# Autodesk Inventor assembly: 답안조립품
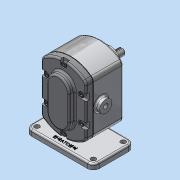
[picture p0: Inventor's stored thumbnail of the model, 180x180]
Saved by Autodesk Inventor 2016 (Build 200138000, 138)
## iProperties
Created: 2019-03
Part Number: 답안조립품
Material: 일반
Document SubType Name: Assembly
Designer: Administrator
Author: Administrator
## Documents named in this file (11)
- C:\Users\Administrator\Desktop\490307V101\답안조립품.iam
- C:\Users\Administrator\Desktop\490307V101\본체.ipt
- C:\Users\Administrator\Desktop\490307V101\개스킷.ipt
- C:\Users\Administrator\Desktop\490307V101\메인축.ipt
- C:\Users\Administrator\Desktop\490307V101\베어링부시.ipt
- C:\Users\Administrator\Desktop\490307V101\볼트 M5.ipt
- C:\Users\Administrator\Desktop\490307V101\서브축.ipt
- C:\Users\Administrator\Desktop\490307V101\스퍼기어.ipt
- C:\Users\Administrator\Desktop\490307V101\오일 실 16 28 7.ipt
- C:\Users\Administrator\Desktop\490307V101\커버.ipt
- C:\Users\Administrator\Desktop\490307V101\키 6 x 6 x 18.ipt
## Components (1 placed, 1 different names)
1. 개스킷:1
